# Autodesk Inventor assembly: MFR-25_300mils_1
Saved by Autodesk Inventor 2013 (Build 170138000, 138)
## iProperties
Created: 2021-02
Part Number: MFR-25_300mils_1
Document SubType Name: Assembly
Designer: Fede
Author: Fede
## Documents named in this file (2)
- C:\0000 FEDE\16GB\0000 INTERIOR\DE_TMP_BAS\BAS_DTON - demora conexion al energizar\pcb\BOR\turn on\Imported Components\BAS_DTON\MFR-25_300mils_1.iam
- C:\0000 FEDE\16GB\0000 INTERIOR\DE_TMP_BAS\BAS_DTON - demora conexion al energizar\pcb\BOR\turn on\Imported Components\BAS_DTON\MFR-25_300mils.iam
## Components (1 placed, 1 different names)
1. MFR-25_300mils:1 [sub-assembly]
